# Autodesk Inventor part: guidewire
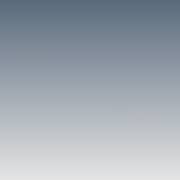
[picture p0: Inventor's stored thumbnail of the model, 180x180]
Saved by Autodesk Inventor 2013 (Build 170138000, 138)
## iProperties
Created: 2013-11
Part Number: guidewire
Material: Generic
Document SubType Name: Modeling
Designer: Warren
Density: 1 g/cm^3
Author: Warren
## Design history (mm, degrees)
sketch "Sketch1"
  geometry: C1 r 0.02 at (0, 0); 1 further point
  constraints: 1 centre point, 1 coincident
  dimensions: "d0" = 0.04 diameter of C1
extrude "Extrusion1" new body sketch "Sketch1" distance "d2" = 500; taper "d3" = 0 deg
body "Solid1"
